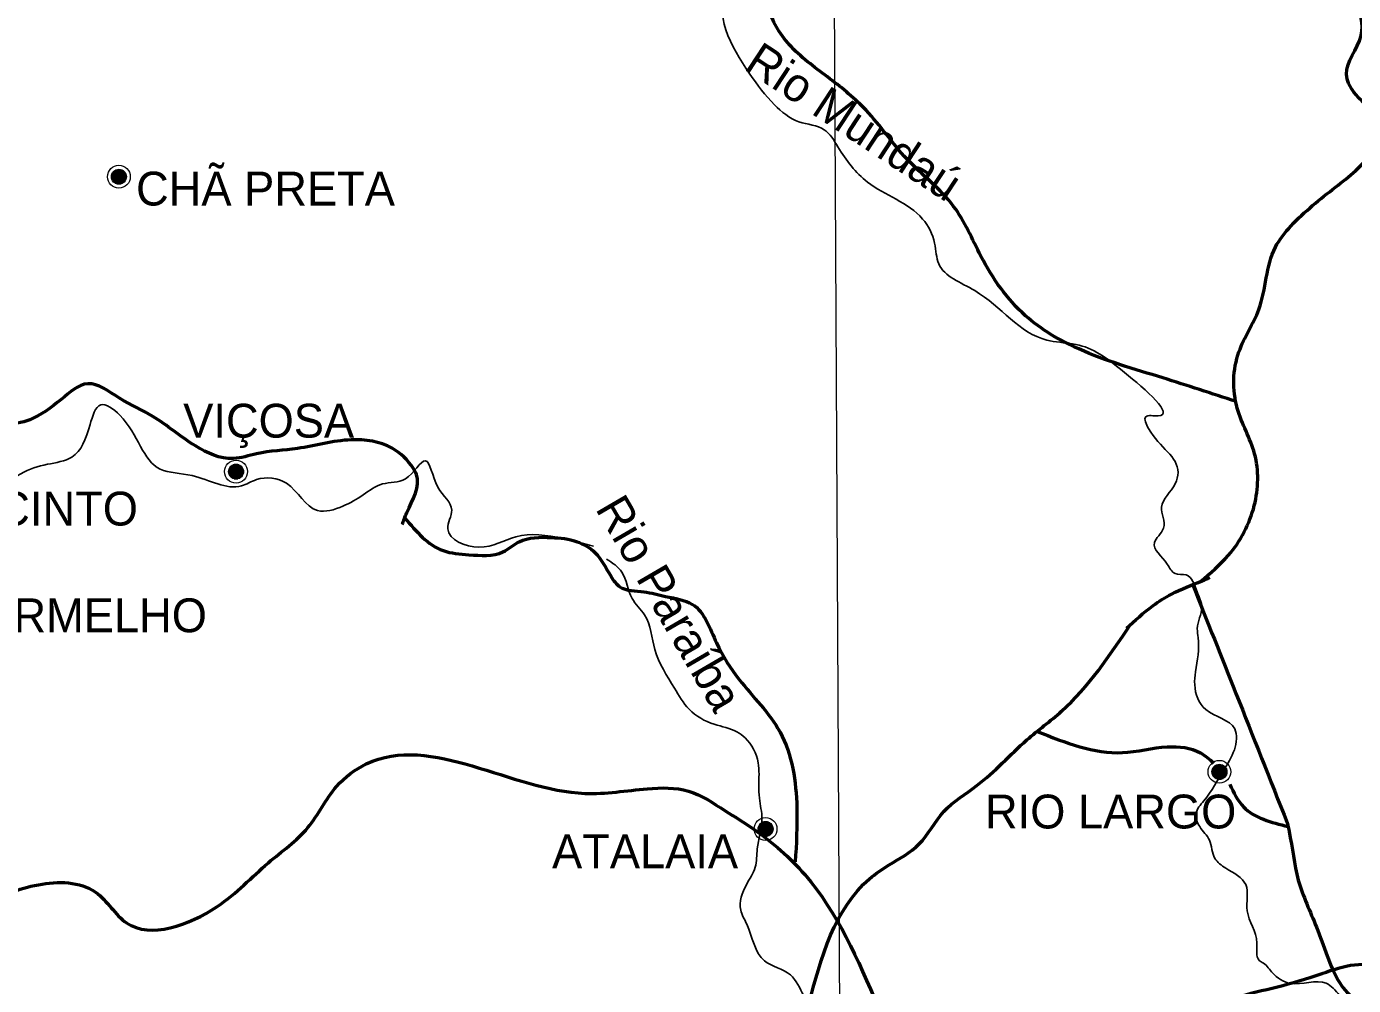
# Model space of a CAD drawing. Extents: x 512883 to 1063249, y 8784064 to 9081064.
# Drawn here: x 792958 to 851806, y 8938828 to 8981350 of the extents above; entities that cross this region are included whole.
import ezdxf

# ---------------------------------------------------------------- set-up
doc = ezdxf.new("R2010")
doc.units = 0
doc.header["$LTSCALE"] = 600
doc.linetypes.add('MEDIUM_DASHED', pattern=[4.5, 3, -1.5])
for name, color, linetype, lineweight in [('1', 7, 'Continuous', 25), ('10', 7, 'Continuous', 53), ('13', 7, 'Continuous', 90), ('4', 7, 'Continuous', 13), ('5', 7, 'Continuous', 13), ('60', 7, 'Continuous', 25)]:
    doc.layers.add(name, color=color, linetype=linetype, lineweight=lineweight)
doc.layers.add('14', color=7, linetype='Continuous')

msp = doc.modelspace()

# ---------------------------------------------------------------- linework, layer by layer
at = {"layer": '1', "lineweight": 13}
msp.add_line((828480.7, 9039622), (829566.9, 8831691.5), dxfattribs=at)
at = {"layer": '10'}
for points in [[(845019.7, 8956739.4), (846265.2, 8957911.5), (847406.7, 8960106.4), (847421.5, 8962401.9), (846655.5, 8964423.7), (846728.2, 8966928.1), (847611.9, 8968809.1), (848345.1, 8971566.1), (849038.1, 8972507.4), (851008.9, 8974225), (852678.9, 8975879), (853028.9, 8976944.4), (852030.2, 8978193.3), (851496.1, 8979235), (852140.4, 8980948.2), (851842.9, 8982408.1), (850670.3, 8983030.3), (849119.1, 8983359.2), (848846, 8984422.6), (849983.5, 8985156.7), (854563.6, 8990826.8), (856059.2, 8993711.5), (857398.3, 8996199.1), (858506.1, 8997809.6), (860401.3, 8999088.7), (864451.3, 9003709.9)], [(846608.8, 8964716.3), (843344.4, 8965769.4), (839632, 8967051.3), (837264.2, 8968525.3), (835285.3, 8971169.2), (834075.1, 8973377.3), (832001.8, 8975478.3), (830189, 8977642.8), (828585.8, 8979035.8), (826881.9, 8980449.3), (825898.7, 8982115.6), (826015.6, 8984265.4), (826401.6, 8985706.6), (826979.7, 8987962.2), (826549.3, 8990527.6), (825448.5, 8993737.8), (825438.5, 8993772)], [(809616.9, 8959267.4), (809825.5, 8959797.2), (810249, 8961488.9), (810105.3, 8961759.7), (809170.8, 8962654), (807357.9, 8963023.8), (804970.4, 8962640.4), (803164.1, 8962405.1), (802121.3, 8962193), (800446.9, 8962751), (798563.3, 8964059.7), (797087.1, 8964868.8), (795673.1, 8965511.1), (794494.9, 8964818.7), (793098, 8963916.8), (790831.3, 8963513), (788586.3, 8962963.2), (786396.8, 8962851.7), (785601.5, 8963892.6), (784625.4, 8964912), (782553, 8965114), (781230, 8964796.7), (779464.4, 8964519.7), (778246.8, 8965580), (777043.4, 8967162.2), (775528.5, 8967845.9), (773570.9, 8966754.4), (771581.8, 8964869.9), (770307.8, 8963759.7), (769400.4, 8962212.5), (767924.2, 8961206.1), (767132.1, 8960139.2), (766642.8, 8958948.2), (765265.7, 8958067.2), (763103.9, 8957267.3), (761887.4, 8956407.7)], [(809734.3, 8959555), (811432, 8958112), (812579.6, 8957927.9), (814085.6, 8958058), (814804.3, 8958498.5), (816229.1, 8958691), (817376.8, 8958506.8), (818165.9, 8958029.4), (818881.1, 8956967.5), (819268.1, 8956509.6), (820335.8, 8956283.5), (821302.8, 8956077.9), (822492.5, 8955727), (823556.6, 8954019.2), (824559.4, 8952394.8), (826374, 8950063.4), (827121.3, 8946706.5), (827050.8, 8944306.1)], [(841737.3, 8954666.4), (842908.2, 8955662.2), (843729.3, 8956184.7), (845093.9, 8956771.3), (845435.1, 8956918)], [(844676.6, 8956591.9), (846594.4, 8951777.3), (848867.5, 8946033.2)], [(827629, 8937926.2), (830350.1, 8943558.5), (831211.3, 8944171.2), (832536.5, 8945088.9), (833646.2, 8946543.3), (835106.1, 8947691.9), (837323.3, 8949716.5), (838862.7, 8950990.1), (841905.5, 8954820.8)], [(777166.8, 8941184.2), (777784, 8941113.6), (781400.4, 8939142.2), (784141.8, 8939936.8), (787923.8, 8940936.4), (791046, 8942397.5), (793482.7, 8943294.7), (796021, 8942961.4), (797391.7, 8941602.9), (801402.2, 8942320.6), (803686.7, 8944268.7), (805438.1, 8945832.3), (806707.2, 8947652.2), (808027.2, 8948651.9), (817723.4, 8947344.6), (820490.2, 8947549.7), (822317.8, 8947447.2), (823942.3, 8946575.7), (825211.4, 8945755.4), (827474, 8943741.2), (830718.6, 8937881.3)], [(837776.5, 8950094.3), (841558.6, 8949152.5), (843565.6, 8949409.4), (845015.6, 8949142.8), (845603.6, 8948685.6)], [(846317.4, 8947748.8), (846931.4, 8946749.1), (848902.9, 8945874.9)], [(848867.5, 8946033.2), (848953.4, 8945649.6), (849359.1, 8943501.5), (850166, 8941417.2), (850642.3, 8940145.8), (851198.4, 8938937.2), (852662.8, 8937376.8), (853704.1, 8935898.6), (854446.4, 8934210.6), (855183.3, 8933002.6), (856322.2, 8931796), (856997.2, 8930733.8), (857571.5, 8929692.3), (857857.2, 8929296.7), (858437.1, 8929569.9), (858168, 8932094.1), (857571, 8935180.7), (856574, 8936283.5), (854606.5, 8937904.8), (853586.3, 8939278.9), (852737.6, 8939693.5), (849869.4, 8939162.5), (846082.2, 8938127.7), (843299.2, 8937158.8), (836103.2, 8937219), (833831.4, 8937274.3), (831233.2, 8937766.7), (829826.1, 8937783.1), (827167.1, 8936982)]]:
    msp.add_spline(points, degree=3, dxfattribs=at)
at = {"layer": '13', "linetype": 'MEDIUM_DASHED', "lineweight": 70}
msp.add_spline([(794561.3, 8984247.3), (793616.3, 8984286), (792392.4, 8982278.7), (790528.1, 8980018.9), (790126.1, 8980017.6), (788955.1, 8978678.2), (787269.9, 8978401.5), (785639, 8978667.5), (783741.9, 8979370.9), (781684.8, 8980011.2), (780098.6, 8979860), (778786.9, 8978520.2), (777001.7, 8978201.4), (775996.1, 8978260.7), (775361.7, 8977465.7), (775246.4, 8976985.3), (773727.5, 8974392.8), (772648.9, 8973784.1), (770940.2, 8973820.3), (769920, 8973378.8), (768383.8, 8972351.3), (766882.2, 8971824.7), (766821.9, 8971824.5)], degree=3, dxfattribs=at)
at = {"layer": '4', "lineweight": 25}
for points in [[(851191, 8938383.9), (850602.3, 8938925.5), (848994.8, 8938925.2), (848220.2, 8939381.5), (847812, 8939817), (847628.5, 8939941.4), (847524.5, 8940708.9), (847093, 8942140), (847028.6, 8943301.6), (846151.5, 8944027.4), (845661.9, 8944462.9), (845415.3, 8945271.8), (844986.3, 8945873.3), (844821.8, 8946454.1), (845166.1, 8947014.2), (846057.5, 8948383.3), (846522.9, 8949275.3), (846540.5, 8950208.7), (845256.1, 8951058.9), (844764.5, 8952158.2), (844803.5, 8952739), (844921.2, 8954253.2), (844879.4, 8954647.3), (845080.1, 8955601.4), (844874.6, 8956285.9), (844384.1, 8957032.6), (843895.5, 8957094.7), (843548.4, 8957509.5), (842975.9, 8958463.6), (843381, 8959106.6), (843296.9, 8960040), (843904.3, 8961077.2), (844025, 8961575.1), (842717, 8963524.6), (842593.4, 8964043.2), (843142.7, 8964084.7), (841651.6, 8966013.6), (839348.6, 8967278.5), (838208.6, 8967444.2), (835007.4, 8969642.5), (833416.8, 8970824.5), (833231, 8971737.2), (832698.8, 8972815.7), (830252.2, 8974454), (828945.4, 8976009.4), (828332.7, 8976776.8), (827212.5, 8977129.2), (826131.9, 8977875.8), (825008.6, 8979286.1), (824163.5, 8982998.9), (825197.8, 8984202.1), (825073.8, 8984845.1), (825376.3, 8985778.5), (825466.6, 8989740.3), (824246.1, 8989574.2), (822904, 8989262.8), (821581.4, 8989262.6), (820337, 8990341.1), (819744.2, 8991274.4), (819944.3, 8992415.2), (820451.8, 8992850.9), (821120.8, 8993722.2), (820854.7, 8994261.4), (820608.2, 8995049.6), (819605.7, 8996916.2), (820294.9, 8997808.2), (820821.7, 8998596.5), (821628.5, 9001044.2), (824715.2, 9003222.6), (824854.6, 9004280.5), (822383.3, 9007412.2), (820324.4, 9008677.2), (817614.6, 9009859.1), (815944.4, 9010418.9), (811767.4, 9012326.6), (811665.2, 9012471.8)], [(818100.3, 8958307.5), (816732.1, 8958650.8), (814661, 8958727.6), (813018.1, 8958263.2), (811642.4, 8959072.6), (811814.1, 8959907.9), (811199.8, 8960928.5), (810644.2, 8962095.3), (809768.7, 8961299.5), (808746.2, 8961066.7), (807887.3, 8960583.9), (806988.5, 8960080.2), (805865.1, 8959888.7), (804485, 8961094.6), (803156.7, 8961257.3), (802496.5, 8960983.9), (800300.7, 8961435.9), (798890.6, 8961723.5), (797095.4, 8964117.5), (796246.2, 8964573.9), (795773.6, 8963695.9), (794965.5, 8962253.4), (793883.7, 8961936.8), (792702.5, 8961515.7), (791443, 8960906.4), (790355.7, 8961090.7), (789293.5, 8960816), (788537.4, 8961940.5), (787299.4, 8961206.1), (786894, 8961517.8), (785349.4, 8961241.5), (784078.6, 8961654.8), (783328.8, 8962215.8), (782859.3, 8962861.2), (783232.9, 8963613.7), (783283.5, 8964490.3), (782221.5, 8964194.7), (781234.7, 8964379.3), (780062.5, 8964959.8), (778358.1, 8966415.1), (777133.3, 8968122.4), (776706.2, 8968580.1), (775808.2, 8969808.4), (775064.4, 8969826.9), (774860.3, 8969768.4)], [(833966.8, 8933146.5), (832795.3, 8932826), (831689.9, 8932822.4), (830791.7, 8932256.1), (830030.1, 8932065.8), (830284.9, 8932650.9), (830387.7, 8934258.1), (829394.3, 8935027.1), (829325.7, 8935778.1), (828921.2, 8936006.3), (828540.1, 8935942.5), (827920.1, 8937484.8), (827427.8, 8938380.5), (826834.8, 8939296.8), (825682.2, 8939919.1), (824900.5, 8941544.3), (824632.3, 8942169.5), (824881.1, 8943297.2), (825274.5, 8944070.6), (825366, 8944884.8), (825572.6, 8946200.1), (825461.7, 8947138.8), (825435.6, 8947681.3), (825404.2, 8948703.8), (824829.2, 8949808), (824464.4, 8950078.1), (823455.8, 8950408.7), (822343.1, 8951072.9), (821689.5, 8952009.9), (820826.5, 8953718.3), (820367.2, 8955261.1), (819816.5, 8955989.7), (819361.4, 8957156.8), (818678.4, 8957737.7)]]:
    msp.add_spline(points, degree=3, dxfattribs=at)
at = {"layer": '4'}
msp.add_spline([(830241.8, 8913061.2), (829149, 8913536.4), (827439.7, 8913177.5), (826147.8, 8913402.5), (825384.3, 8913171.3), (824554.1, 8913584.9), (823759.2, 8914518.6), (822827.3, 8915035.8), (821955, 8915636.5), (821248.5, 8915759.2), (819586.9, 8916711.1), (818533.7, 8917269.5), (817362.3, 8917536.4), (815944.8, 8918260.2), (814975.2, 8918506.9), (813404.4, 8918398.2), (812633.1, 8918978.3), (812224, 8919601.2), (811906.3, 8921202), (811391.5, 8922344.6), (811100.9, 8923217.4), (810271.4, 8923568.6), (809585.4, 8923649.7), (808316.8, 8923562.7), (807869.8, 8923935.8), (806863.7, 8923787.1), (805966.1, 8924928.5), (805085.5, 8926382.1), (804213.4, 8926961.9), (803507.4, 8927043), (803043.7, 8927062.4), (801988.8, 8925707), (801265.4, 8925496.8), (800038, 8925305.8), (799427.5, 8925928.1), (797719, 8927566.3), (796560.5, 8928582.1), (796030.6, 8929204.6), (795985.9, 8929662.2), (795818.1, 8930348.1), (794959.1, 8931656.1), (795129.4, 8932800.8), (795079.4, 8933799.2), (794428.2, 8934462.9), (793375.3, 8934979.8), (792885.7, 8935602.4), (792718.7, 8936205.2), (792849.5, 8937266.5), (792761.8, 8937994.3), (791766, 8938865), (791496.6, 8939633.9), (791206.3, 8940486), (789987, 8941543.2), (789646.5, 8941334.2), (788960.3, 8941436.1), (788819.1, 8941456.5), (788590.6, 8942163.1), (788458, 8943369.2), (788382.4, 8943559.9)], degree=3, dxfattribs=at)
at = {"layer": '5'}
for p, q in [((796747.5, 8974819.1), (797360.7, 8974819.4)), ((796761.9, 8974849.1), (797346.6, 8974849.1)), ((796780.2, 8974879.1), (797328.3, 8974879.1)), ((796804.2, 8974909.1), (797304.6, 8974909.1)), ((796833.3, 8974939.1), (797274.9, 8974939.1)), ((796872.9, 8974969.1), (797235.3, 8974969.1)), ((796930.2, 8974999.1), (797178, 8974999.1)), ((796721.7, 8974699.1), (797386.5, 8974699.1)), ((796722.3, 8974669.1), (797386.2, 8974669.1)), ((796723.8, 8974729.1), (797384.4, 8974729.1)), ((796725.3, 8974639.1), (797382.9, 8974639.1)), ((796728.6, 8974759.1), (797379.6, 8974759.1)), ((796731.3, 8974609.1), (797376.9, 8974609.1)), ((796736.7, 8974789.1), (797371.5, 8974789.1)), ((796740.3, 8974579.1), (797367.9, 8974579.1)), ((796752.9, 8974549.1), (797355.6, 8974549.4)), ((796768.8, 8974519.1), (797339.4, 8974519.1)), ((796789.5, 8974489.1), (797319, 8974489.4)), ((796814.7, 8974458.8), (797293.8, 8974459.1)), ((796848, 8974429.1), (797260.2, 8974429.1)), ((796893, 8974399.1), (797215.2, 8974399.1)), ((796966.8, 8974369.1), (797141.1, 8974369.1)), ((802068.2, 8961892.5), (802430.6, 8961892.5)), ((802125.5, 8961922.5), (802373.2, 8961922.5)), ((801917, 8961622.5), (802581.8, 8961622.5)), ((801917.6, 8961592.5), (802581.5, 8961592.5)), ((801919.1, 8961652.5), (802579.7, 8961652.5)), ((801920.6, 8961562.5), (802578.2, 8961562.5)), ((801923.8, 8961682.5), (802574.8, 8961682.5)), ((801926.6, 8961532.5), (802572.2, 8961532.5)), ((801932, 8961712.5), (802566.8, 8961712.5)), ((801935.6, 8961502.5), (802563.2, 8961502.5)), ((801942.8, 8961742.5), (802556, 8961742.8)), ((801948.2, 8961472.5), (802550.8, 8961472.8)), ((801957.2, 8961772.5), (802541.8, 8961772.5)), ((801964.1, 8961442.5), (802534.7, 8961442.5)), ((801975.5, 8961802.5), (802523.6, 8961802.5)), ((801984.8, 8961412.5), (802514.2, 8961412.8)), ((801999.5, 8961832.5), (802499.8, 8961832.5)), ((802010, 8961382.2), (802489.1, 8961382.5)), ((802028.6, 8961862.5), (802470.2, 8961862.5)), ((802043.2, 8961352.5), (802455.5, 8961352.5)), ((802088.2, 8961322.5), (802410.5, 8961322.5)), ((802162.1, 8961292.5), (802336.3, 8961292.5)), ((845531.1, 8948340.9), (846191.7, 8948340.9)), ((845535.9, 8948370.9), (846186.9, 8948370.9)), ((845544, 8948400.9), (846178.8, 8948400.9)), ((845554.8, 8948430.9), (846168, 8948431.2)), ((845569.2, 8948460.9), (846153.9, 8948460.9)), ((845587.5, 8948490.9), (846135.6, 8948490.9)), ((845611.5, 8948520.9), (846111.9, 8948520.9)), ((845640.6, 8948550.9), (846082.2, 8948550.9)), ((845680.2, 8948580.9), (846042.6, 8948580.9)), ((845737.5, 8948610.9), (845985.3, 8948610.9)), ((845529, 8948310.9), (846193.8, 8948310.9)), ((845529.6, 8948280.9), (846193.5, 8948280.9)), ((845532.6, 8948250.9), (846190.2, 8948250.9)), ((845538.6, 8948220.9), (846184.2, 8948220.9)), ((845547.6, 8948190.9), (846175.2, 8948190.9)), ((845560.2, 8948160.9), (846162.9, 8948161.2)), ((845576.1, 8948130.9), (846146.7, 8948130.9)), ((845596.8, 8948100.9), (846126.3, 8948101.2)), ((845622, 8948070.6), (846101.1, 8948070.9)), ((845655.3, 8948040.9), (846067.5, 8948040.9)), ((845700.3, 8948010.9), (846022.5, 8948010.9)), ((845774.1, 8947980.9), (845948.4, 8947980.9)), ((825484.2, 8945986.9), (825984.6, 8945986.9)), ((825513.3, 8946016.9), (825954.9, 8946016.9)), ((825552.9, 8946046.9), (825915.3, 8946046.9)), ((825610.2, 8946076.9), (825858, 8946076.9)), ((825401.7, 8945776.9), (826066.5, 8945776.9)), ((825402.3, 8945746.9), (826066.2, 8945746.9)), ((825403.8, 8945806.9), (826064.4, 8945806.9)), ((825405.3, 8945716.9), (826062.9, 8945716.9)), ((825408.6, 8945836.9), (826059.6, 8945836.9)), ((825411.3, 8945686.9), (826056.9, 8945686.9)), ((825416.7, 8945866.9), (826051.5, 8945866.9)), ((825420.3, 8945656.9), (826047.9, 8945656.9)), ((825427.5, 8945896.9), (826040.7, 8945897.2)), ((825432.9, 8945626.9), (826035.6, 8945627.2)), ((825441.9, 8945926.9), (826026.6, 8945926.9)), ((825448.8, 8945596.9), (826019.4, 8945596.9)), ((825460.2, 8945956.9), (826008.3, 8945956.9)), ((825469.5, 8945566.9), (825999, 8945567.2)), ((825494.7, 8945536.6), (825973.8, 8945536.9)), ((825528, 8945506.9), (825940.2, 8945506.9)), ((825573, 8945476.9), (825895.2, 8945476.9)), ((825646.8, 8945446.9), (825821.1, 8945446.9))]:
    msp.add_line(p, q, dxfattribs=at)
for centre, radius in [((797054.2, 8974690.1), 506.1), ((797054.2, 8974690.1), 332.9), ((802249.4, 8961613.5), 506.1), ((802249.4, 8961613.5), 332.9), ((845861.5, 8948301.9), 506.1), ((845861.5, 8948301.9), 332.9), ((825734.2, 8945767.9), 506.1), ((825734.2, 8945767.9), 332.9)]:
    msp.add_circle(centre, radius, dxfattribs=at)
at = {"layer": '60'}
msp.add_spline([(928828.8, 9027989.5), (927727.3, 9017705.9), (905698.2, 8975836.8), (863108.4, 8926255), (823455.9, 8876673.2), (798489.5, 8846556.8), (787107.7, 8828193.2)], degree=3, dxfattribs=at)
msp.add_spline([(928828.8, 9027989.5), (927727.3, 9017705.9), (905698.2, 8975836.8), (863108.4, 8926255), (823455.9, 8876673.2), (798489.5, 8846556.8), (787107.7, 8828193.2)], degree=3, dxfattribs=at)

# ---------------------------------------------------------------- texts
at = {"layer": '14'}
for s, rotation, p in [('Rio Mundaú', 326.722, (824722.7, 8979473.1)), ('Rio Paraíba', 300.248, (818158.8, 8959977.2))]:
    msp.add_text(s, height=1500, rotation=rotation, dxfattribs=at).set_placement(p)
at = {"layer": '5'}
for s, p in [('CHÃ PRETA', (797815.6, 8973414.4)), ('VIÇOSA', (799907, 8963121.4)), ('PAULO JACINTO', (781961.8, 8959223.7)), ('MAR VERMELHO', (784687.5, 8954491.6)), ('RIO LARGO', (835464.5, 8945789.9)), ('ATALAIA', (816264.8, 8944025.7))]:
    msp.add_text(s, height=1500, dxfattribs=at).set_placement(p)

doc.saveas('drawing.dxf')
